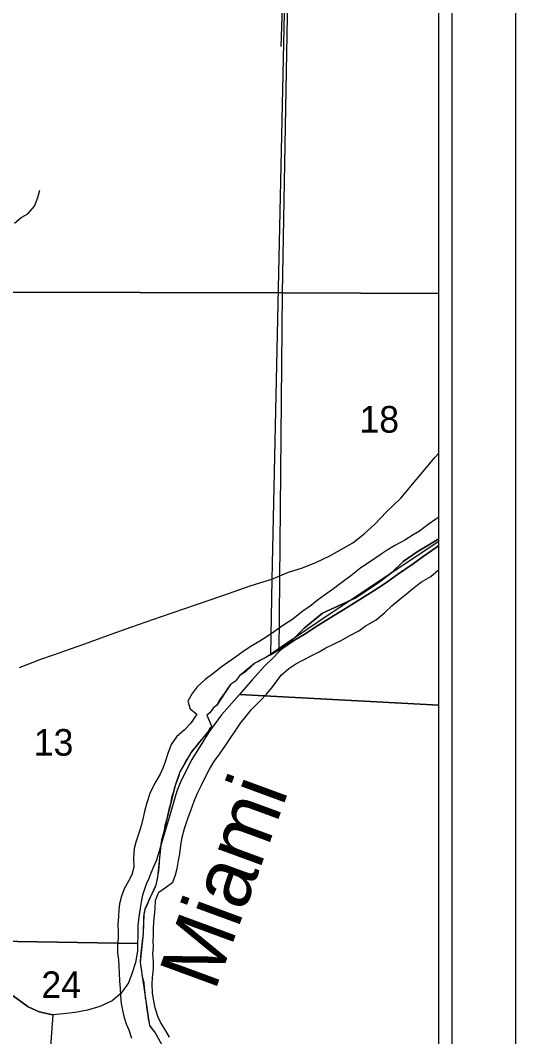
# Model space of a CAD drawing. Extents: x 0 to 34, y -2.3 to 22.
# Drawn here: x 8.222 to 9, y 17.166 to 18.764 of the extents above; entities that cross this region are included whole.
import ezdxf

# ---------------------------------------------------------------- set-up
doc = ezdxf.new("R2010")
doc.units = 0
for name, color, linetype in [('GM_X_Corporation', 7, 'Continuous'), ('GM_X_County', 7, 'Continuous'), ('GM_X_Major_River', 7, 'Continuous'), ('GM_X_Major_River_Text', 7, 'Continuous'), ('GM_X_Minor_River', 7, 'Continuous'), ('GM_X_Section', 7, 'Continuous'), ('GM_X_Section_Text', 7, 'Continuous'), ('GM_X_State_Route', 7, 'Continuous'), ('GM_X_Township', 7, 'Continuous'), ('GM_X_Township_Road', 7, 'Continuous'), ('SH_Data', 7, 'Continuous')]:
    doc.layers.add(name, color=color, linetype=linetype)

msp = doc.modelspace()

# ---------------------------------------------------------------- linework, layer by layer
at = {"layer": 'GM_X_Corporation'}
for p, q in [((8.8792, 17.9444), (8.7056, 17.8282)), ((8.8792, 14.574), (8.8792, 17.9444)), ((8.7056, 17.8282), (8.6403, 17.7846)), ((8.6403, 17.7846), (8.6086, 17.7626)), ((8.5903, 17.7529), (8.5849, 17.7484)), ((8.5951, 17.755), (8.5903, 17.7529)), ((8.6013, 17.7586), (8.5951, 17.755)), ((8.6086, 17.7626), (8.6013, 17.7586)), ((8.576, 17.74), (8.5664, 17.7333)), ((8.5849, 17.7484), (8.576, 17.74)), ((8.5598, 17.7248), (8.5522, 17.7195)), ((8.5664, 17.7333), (8.5598, 17.7248)), ((8.5424, 17.7059), (8.5381, 17.6994)), ((8.5471, 17.7132), (8.5424, 17.7059)), ((8.5522, 17.7195), (8.5471, 17.7132)), ((8.5355, 17.6958), (8.5304, 17.6867)), ((8.5381, 17.6994), (8.5355, 17.6958)), ((8.5197, 17.6747), (8.5149, 17.6714)), ((8.5248, 17.6823), (8.5197, 17.6747)), ((8.5304, 17.6867), (8.5248, 17.6823)), ((8.5149, 17.6714), (8.5225, 17.6531)), ((8.5172, 17.6456), (8.5111, 17.6378)), ((8.5193, 17.6498), (8.5172, 17.6456)), ((8.5225, 17.6531), (8.5193, 17.6498)), ((8.5004, 17.6254), (8.4954, 17.6194)), ((8.5067, 17.6329), (8.5004, 17.6254)), ((8.5111, 17.6378), (8.5067, 17.6329)), ((8.4896, 17.6122), (8.4855, 17.6049)), ((8.4921, 17.616), (8.4896, 17.6122)), ((8.4954, 17.6194), (8.4921, 17.616)), ((8.4802, 17.5959), (8.4763, 17.5882)), ((8.4826, 17.6003), (8.4802, 17.5959)), ((8.4855, 17.6049), (8.4826, 17.6003)), ((8.472, 17.5813), (8.471, 17.5758)), ((8.4722, 17.582), (8.472, 17.5813)), ((8.4763, 17.5882), (8.4722, 17.582)), ((8.4649, 17.5607), (8.4637, 17.5559)), ((8.466, 17.5635), (8.4649, 17.5607)), ((8.471, 17.5758), (8.466, 17.5635)), ((8.4618, 17.5493), (8.4596, 17.5415)), ((8.4637, 17.5559), (8.4618, 17.5493)), ((8.4576, 17.532), (8.4554, 17.5231)), ((8.4596, 17.5415), (8.4576, 17.532)), ((8.4532, 17.5137), (8.4514, 17.5059)), ((8.4554, 17.5231), (8.4532, 17.5137)), ((8.4491, 17.4975), (8.4477, 17.4892)), ((8.4514, 17.5059), (8.4491, 17.4975)), ((8.4452, 17.4806), (8.4438, 17.4752)), ((8.4477, 17.4892), (8.4452, 17.4806)), ((8.4427, 17.469), (8.4408, 17.4529)), ((8.443, 17.4718), (8.4427, 17.469)), ((8.4438, 17.4752), (8.443, 17.4718)), ((8.4408, 17.4529), (8.4403, 17.4476)), ((8.4398, 17.439), (8.439, 17.4263)), ((8.4399, 17.4434), (8.4398, 17.439)), ((8.4403, 17.4476), (8.4399, 17.4434)), ((8.439, 17.4263), (8.4371, 17.4143)), ((8.4346, 17.404), (8.4311, 17.395)), ((8.4371, 17.4143), (8.4346, 17.404)), ((8.4274, 17.3881), (8.425, 17.3829)), ((8.4311, 17.395), (8.4274, 17.3881)), ((8.4217, 17.3739), (8.4177, 17.3664)), ((8.4234, 17.3799), (8.4217, 17.3739)), ((8.425, 17.3829), (8.4234, 17.3799)), ((8.416, 17.3585), (8.4154, 17.3526)), ((8.417, 17.362), (8.416, 17.3585)), ((8.4177, 17.3664), (8.417, 17.362)), ((8.4154, 17.3526), (8.4148, 17.3282)), ((8.4148, 17.3282), (8.4135, 17.3166)), ((8.4122, 17.3066), (8.4112, 17.2972)), ((8.4126, 17.311), (8.4122, 17.3066)), ((8.4135, 17.3166), (8.4126, 17.311)), ((8.4107, 17.2919), (8.4102, 17.2831)), ((8.4112, 17.2972), (8.4107, 17.2919)), ((8.4102, 17.2831), (8.4102, 17.2821)), ((8.4102, 17.2821), (8.4119, 17.273)), ((8.4119, 17.273), (8.4122, 17.2683)), ((8.4122, 17.2683), (8.4129, 17.2639)), ((8.4129, 17.2639), (8.4134, 17.2603)), ((8.4134, 17.2603), (8.4157, 17.2507)), ((8.4157, 17.2507), (8.4164, 17.2424)), ((8.4164, 17.2424), (8.4173, 17.2346)), ((8.4173, 17.2346), (8.4181, 17.2269)), ((8.4181, 17.2269), (8.419, 17.2221)), ((8.419, 17.2221), (8.4203, 17.213)), ((8.4203, 17.213), (8.4205, 17.2082)), ((8.4205, 17.2082), (8.422, 17.1994)), ((8.422, 17.1994), (8.4225, 17.1938)), ((8.4225, 17.1938), (8.4241, 17.1871)), ((8.4241, 17.1871), (8.4249, 17.1833)), ((8.4249, 17.1833), (8.4275, 17.1795)), ((8.4275, 17.1795), (8.4335, 17.1719)), ((8.4335, 17.1719), (8.4379, 17.1644))]:
    msp.add_line(p, q, dxfattribs=at)
at = {"layer": 'GM_X_County'}
msp.add_line((8.8792, 14.574), (8.8792, 20.8994), dxfattribs=at)
at = {"layer": 'GM_X_Major_River'}
for p, q in [((8.8747, 17.9795), (8.8627, 17.9707)), ((8.8792, 17.9825), (8.8747, 17.9795)), ((8.8487, 17.9604), (8.8391, 17.9546)), ((8.8627, 17.9707), (8.8487, 17.9604)), ((8.8259, 17.9462), (8.8101, 17.9379)), ((8.8391, 17.9546), (8.8259, 17.9462)), ((8.7981, 17.9306), (8.7885, 17.9244)), ((8.8101, 17.9379), (8.7981, 17.9306)), ((8.7722, 17.913), (8.7567, 17.9028)), ((8.7885, 17.9244), (8.7722, 17.913)), ((8.7567, 17.9028), (8.7411, 17.8903)), ((8.8665, 17.8892), (8.879, 17.8999)), ((8.879, 17.8999), (8.8792, 17.9)), ((8.7411, 17.8903), (8.7272, 17.8796)), ((8.8387, 17.8701), (8.8522, 17.8808)), ((8.8522, 17.8808), (8.8665, 17.8892)), ((8.7136, 17.8697), (8.6996, 17.8598)), ((8.7272, 17.8796), (8.7136, 17.8697)), ((8.8285, 17.8617), (8.8387, 17.8701)), ((8.6884, 17.8514), (8.6767, 17.8418)), ((8.6996, 17.8598), (8.6884, 17.8514)), ((8.8056, 17.8433), (8.8181, 17.8536)), ((8.8181, 17.8536), (8.8285, 17.8617)), ((8.6663, 17.8352), (8.6499, 17.822)), ((8.6767, 17.8418), (8.6663, 17.8352)), ((8.7807, 17.8211), (8.7943, 17.8325)), ((8.7943, 17.8325), (8.8056, 17.8433)), ((8.6499, 17.822), (8.6352, 17.8125)), ((8.7637, 17.8109), (8.7807, 17.8211)), ((8.6213, 17.8029), (8.6097, 17.7949)), ((8.6352, 17.8125), (8.6213, 17.8029)), ((8.7397, 17.7967), (8.7536, 17.8036)), ((8.7536, 17.8036), (8.7637, 17.8109)), ((8.5981, 17.7876), (8.5857, 17.7803)), ((8.6097, 17.7949), (8.5981, 17.7876)), ((8.715, 17.7833), (8.7258, 17.7887)), ((8.7258, 17.7887), (8.7397, 17.7967)), ((8.5733, 17.7723), (8.5597, 17.7624)), ((8.5857, 17.7803), (8.5733, 17.7723)), ((8.6807, 17.7656), (8.6915, 17.771)), ((8.6915, 17.771), (8.7019, 17.7772)), ((8.7019, 17.7772), (8.715, 17.7833)), ((8.5477, 17.7539), (8.5376, 17.7466)), ((8.5597, 17.7624), (8.5477, 17.7539)), ((8.6545, 17.7518), (8.6668, 17.7583)), ((8.6668, 17.7583), (8.6807, 17.7656)), ((8.5264, 17.7378), (8.5124, 17.7275)), ((8.5376, 17.7466), (8.5264, 17.7378)), ((8.6319, 17.7342), (8.6436, 17.7445)), ((8.6436, 17.7445), (8.6545, 17.7518)), ((8.5124, 17.7275), (8.4999, 17.7156)), ((8.617, 17.7144), (8.6244, 17.7241)), ((8.6244, 17.7241), (8.6319, 17.7342)), ((8.4917, 17.7052), (8.4852, 17.6932)), ((8.4999, 17.7156), (8.4917, 17.7052)), ((8.5989, 17.6939), (8.6087, 17.7043)), ((8.6087, 17.7043), (8.617, 17.7144)), ((8.4852, 17.6932), (8.4887, 17.6813)), ((8.5852, 17.6799), (8.5989, 17.6939)), ((8.4887, 17.6813), (8.4991, 17.6727)), ((8.4991, 17.6727), (8.4896, 17.6585)), ((8.5769, 17.6694), (8.5852, 17.6799)), ((8.4896, 17.6585), (8.4798, 17.6481)), ((8.5592, 17.6463), (8.5679, 17.6586)), ((8.5679, 17.6586), (8.5769, 17.6694)), ((8.4798, 17.6481), (8.467, 17.6374)), ((8.5517, 17.6347), (8.5592, 17.6463)), ((8.459, 17.625), (8.4537, 17.6111)), ((8.467, 17.6374), (8.459, 17.625)), ((8.543, 17.622), (8.5517, 17.6347)), ((8.4537, 17.6111), (8.45, 17.5994)), ((8.5259, 17.5977), (8.535, 17.61)), ((8.535, 17.61), (8.543, 17.622)), ((8.45, 17.5994), (8.4463, 17.5889)), ((8.5188, 17.5854), (8.5259, 17.5977)), ((8.4418, 17.5787), (8.433, 17.5641)), ((8.4463, 17.5889), (8.4418, 17.5787)), ((8.512, 17.5734), (8.5188, 17.5854)), ((8.433, 17.5641), (8.4254, 17.5483)), ((8.5059, 17.5602), (8.512, 17.5734)), ((8.4254, 17.5483), (8.4204, 17.5332)), ((8.495, 17.5358), (8.5003, 17.5486)), ((8.5003, 17.5486), (8.5059, 17.5602)), ((8.4204, 17.5332), (8.417, 17.52)), ((8.4896, 17.5215), (8.495, 17.5358)), ((8.417, 17.52), (8.4148, 17.5102)), ((8.4855, 17.5105), (8.4896, 17.5215)), ((8.4118, 17.4973), (8.4073, 17.4841)), ((8.4148, 17.5102), (8.4118, 17.4973)), ((8.4797, 17.4932), (8.4855, 17.5105)), ((8.4073, 17.4841), (8.4035, 17.4717)), ((8.4763, 17.4796), (8.4797, 17.4932)), ((8.4035, 17.4717), (8.4006, 17.4618)), ((8.4722, 17.4534), (8.4741, 17.4663)), ((8.4741, 17.4663), (8.4763, 17.4796)), ((8.4006, 17.4618), (8.3998, 17.4466)), ((8.4704, 17.4425), (8.4722, 17.4534)), ((8.3998, 17.4466), (8.4001, 17.4322)), ((8.4681, 17.4303), (8.4704, 17.4425)), ((8.3968, 17.4201), (8.3916, 17.4103)), ((8.4001, 17.4322), (8.3968, 17.4201)), ((8.4614, 17.4084), (8.4659, 17.4201)), ((8.4659, 17.4201), (8.4681, 17.4303)), ((8.3916, 17.4103), (8.3848, 17.3983)), ((8.4397, 17.393), (8.4514, 17.4015)), ((8.4514, 17.4015), (8.4614, 17.4084)), ((8.381, 17.3866), (8.3776, 17.3746)), ((8.3848, 17.3983), (8.381, 17.3866)), ((8.4344, 17.3802), (8.4397, 17.393)), ((8.3776, 17.3746), (8.3766, 17.3651)), ((8.4337, 17.3666), (8.4344, 17.3802)), ((8.376, 17.3548), (8.3752, 17.3415)), ((8.3766, 17.3651), (8.376, 17.3548)), ((8.4316, 17.3465), (8.4326, 17.3563)), ((8.4326, 17.3563), (8.4337, 17.3666)), ((8.3752, 17.3415), (8.3757, 17.3305)), ((8.4309, 17.3354), (8.4316, 17.3465)), ((8.3754, 17.321), (8.3743, 17.3092)), ((8.3757, 17.3305), (8.3754, 17.321)), ((8.4308, 17.316), (8.431, 17.3255)), ((8.431, 17.3255), (8.4309, 17.3354)), ((8.3743, 17.3092), (8.3744, 17.2978)), ((8.4302, 17.2966), (8.4309, 17.3065)), ((8.4309, 17.3065), (8.4308, 17.316)), ((8.3744, 17.2978), (8.376, 17.2867)), ((8.431, 17.2837), (8.4302, 17.2966)), ((8.376, 17.2867), (8.3768, 17.2764)), ((8.3768, 17.2764), (8.3773, 17.2661)), ((8.4311, 17.2726), (8.431, 17.2837)), ((8.3773, 17.2661), (8.3777, 17.2532)), ((8.4289, 17.2483), (8.4296, 17.259)), ((8.4296, 17.259), (8.4311, 17.2726)), ((8.3777, 17.2532), (8.3785, 17.2413)), ((8.3785, 17.2413), (8.3794, 17.2299)), ((8.4297, 17.2346), (8.4289, 17.2483)), ((8.3794, 17.2299), (8.3805, 17.2177)), ((8.4316, 17.2216), (8.4297, 17.2346)), ((8.3805, 17.2177), (8.3822, 17.2074)), ((8.4336, 17.2109), (8.4316, 17.2216)), ((8.4381, 17.1975), (8.4336, 17.2109)), ((8.3822, 17.2074), (8.3846, 17.1974)), ((8.3846, 17.1974), (8.388, 17.1859)), ((8.4428, 17.1875), (8.4381, 17.1975)), ((8.388, 17.1859), (8.3923, 17.1763)), ((8.4504, 17.1747), (8.4428, 17.1875)), ((8.3923, 17.1763), (8.3965, 17.1636)), ((8.4563, 17.165), (8.4504, 17.1747))]:
    msp.add_line(p, q, dxfattribs=at)
at = {"layer": 'GM_X_Minor_River'}
for p, q in [((8.2494, 18.485), (8.2523, 18.4964)), ((8.2335, 18.4596), (8.2444, 18.4715)), ((8.2444, 18.4715), (8.2494, 18.485)), ((8.2234, 18.4534), (8.2335, 18.4596)), ((8.2129, 18.4445), (8.2234, 18.4534))]:
    msp.add_line(p, q, dxfattribs=at)
at = {"layer": 'GM_X_Section'}
for p, q in [((8.6506, 19.3353), (8.6333, 18.3353)), ((8.6506, 19.3353), (8.6333, 18.3353)), ((8.8792, 18.3339), (8.8792, 19.3331)), ((8.6333, 18.3353), (7.6261, 18.3379)), ((7.6261, 18.3379), (8.6333, 18.3353)), ((8.6333, 18.3353), (8.6279, 17.771)), ((8.6333, 18.3353), (8.6279, 17.771)), ((8.6333, 18.3353), (8.8792, 18.3339)), ((8.8792, 18.3339), (8.6333, 18.3353)), ((8.8792, 17.9377), (8.8792, 18.3339)), ((8.8753, 17.935), (8.8545, 17.9204)), ((8.8545, 17.9204), (8.8753, 17.935)), ((8.8792, 17.9377), (8.8753, 17.935)), ((8.8753, 17.935), (8.8792, 17.9377)), ((8.8792, 17.6869), (8.8792, 17.9377)), ((8.8545, 17.9204), (8.8391, 17.9093)), ((8.8391, 17.9093), (8.8545, 17.9204)), ((8.8391, 17.9093), (8.8144, 17.8921)), ((8.8144, 17.8921), (8.8391, 17.9093)), ((8.8144, 17.8921), (8.7955, 17.8785)), ((8.7955, 17.8785), (8.8144, 17.8921)), ((8.7763, 17.8661), (8.751, 17.8504)), ((8.751, 17.8504), (8.7763, 17.8661)), ((8.7955, 17.8785), (8.7763, 17.8661)), ((8.7763, 17.8661), (8.7955, 17.8785)), ((8.751, 17.8504), (8.7329, 17.839)), ((8.7329, 17.839), (8.751, 17.8504)), ((8.7329, 17.839), (8.7141, 17.8273)), ((8.7141, 17.8273), (8.7329, 17.839)), ((8.7141, 17.8273), (8.6891, 17.812)), ((8.6891, 17.812), (8.7141, 17.8273)), ((8.6891, 17.812), (8.6679, 17.7981)), ((8.6679, 17.7981), (8.6891, 17.812)), ((8.6526, 17.789), (8.6426, 17.7824)), ((8.6426, 17.7824), (8.6526, 17.789)), ((8.6679, 17.7981), (8.6526, 17.789)), ((8.6526, 17.789), (8.6679, 17.7981)), ((8.6279, 17.771), (8.6186, 17.761)), ((8.6279, 17.771), (8.6186, 17.761)), ((8.6345, 17.7765), (8.6279, 17.771)), ((8.6279, 17.771), (8.6345, 17.7765)), ((8.6426, 17.7824), (8.6345, 17.7765)), ((8.6345, 17.7765), (8.6426, 17.7824)), ((8.6186, 17.761), (8.6054, 17.748)), ((8.6186, 17.761), (8.6054, 17.748)), ((8.6054, 17.748), (8.586, 17.7265)), ((8.6054, 17.748), (8.586, 17.7265)), ((8.586, 17.7265), (8.5662, 17.7038)), ((8.586, 17.7265), (8.5662, 17.7038)), ((8.5662, 17.7038), (8.5381, 17.6715)), ((8.5662, 17.7038), (8.5381, 17.6715)), ((8.5662, 17.7038), (8.8792, 17.6869)), ((8.8792, 17.6869), (8.5662, 17.7038)), ((8.8792, 16.6052), (8.8792, 17.6869)), ((8.5381, 17.6715), (8.5182, 17.6443)), ((8.5381, 17.6715), (8.5182, 17.6443)), ((8.5182, 17.6443), (8.5084, 17.6294)), ((8.5182, 17.6443), (8.5084, 17.6294)), ((8.5084, 17.6294), (8.4915, 17.6017)), ((8.5084, 17.6294), (8.4915, 17.6017)), ((8.4915, 17.6017), (8.4752, 17.5695)), ((8.4915, 17.6017), (8.4752, 17.5695)), ((8.472, 17.562), (8.468, 17.5519)), ((8.472, 17.562), (8.468, 17.5519)), ((8.4752, 17.5695), (8.472, 17.562)), ((8.4752, 17.5695), (8.472, 17.562)), ((8.468, 17.5519), (8.4623, 17.5338)), ((8.468, 17.5519), (8.4623, 17.5338)), ((8.4623, 17.5338), (8.4561, 17.512)), ((8.4623, 17.5338), (8.4561, 17.512)), ((8.4561, 17.512), (8.4503, 17.4928)), ((8.4561, 17.512), (8.4503, 17.4928)), ((8.4503, 17.4928), (8.4409, 17.4608)), ((8.4503, 17.4928), (8.4409, 17.4608)), ((8.438, 17.4507), (8.4352, 17.442)), ((8.438, 17.4507), (8.4352, 17.442)), ((8.4409, 17.4608), (8.438, 17.4507)), ((8.4409, 17.4608), (8.438, 17.4507)), ((8.4312, 17.4327), (8.4271, 17.4229)), ((8.4312, 17.4327), (8.4271, 17.4229)), ((8.4352, 17.442), (8.4312, 17.4327)), ((8.4352, 17.442), (8.4312, 17.4327)), ((8.4271, 17.4229), (8.4239, 17.4143)), ((8.4271, 17.4229), (8.4239, 17.4143)), ((8.4203, 17.4064), (8.4175, 17.3993)), ((8.4203, 17.4064), (8.4175, 17.3993)), ((8.4239, 17.4143), (8.4203, 17.4064)), ((8.4239, 17.4143), (8.4203, 17.4064)), ((8.4138, 17.3883), (8.4121, 17.3801)), ((8.4138, 17.3883), (8.4121, 17.3801)), ((8.4175, 17.3993), (8.4138, 17.3883)), ((8.4175, 17.3993), (8.4138, 17.3883)), ((8.4121, 17.3801), (8.4103, 17.3676)), ((8.4121, 17.3801), (8.4103, 17.3676)), ((8.4081, 17.354), (8.4067, 17.34)), ((8.4081, 17.354), (8.4067, 17.34)), ((8.4103, 17.3676), (8.4081, 17.354)), ((8.4103, 17.3676), (8.4081, 17.354)), ((8.4067, 17.34), (8.4063, 17.3237)), ((8.4067, 17.34), (8.4063, 17.3237)), ((8.4063, 17.3237), (8.406, 17.312)), ((8.4063, 17.3237), (8.406, 17.312)), ((8.406, 17.312), (8.1504, 17.3163)), ((8.1504, 17.3163), (8.406, 17.312)), ((8.406, 17.312), (8.4062, 17.3003)), ((8.406, 17.312), (8.4062, 17.3003)), ((8.4062, 17.3003), (8.4027, 17.2822)), ((8.4062, 17.3003), (8.4027, 17.2822)), ((8.4027, 17.2822), (8.397, 17.2645)), ((8.4027, 17.2822), (8.397, 17.2645)), ((8.397, 17.2645), (8.3918, 17.2506)), ((8.397, 17.2645), (8.3918, 17.2506)), ((8.3918, 17.2506), (8.3796, 17.2334)), ((8.3918, 17.2506), (8.3796, 17.2334)), ((8.2106, 17.2297), (8.2344, 17.2129)), ((8.2344, 17.2129), (8.2106, 17.2297)), ((8.3796, 17.2334), (8.3661, 17.222)), ((8.3796, 17.2334), (8.3661, 17.222)), ((8.2344, 17.2129), (8.2517, 17.2049)), ((8.2517, 17.2049), (8.2344, 17.2129)), ((8.3466, 17.213), (8.3275, 17.2074)), ((8.3466, 17.213), (8.3275, 17.2074)), ((8.3661, 17.222), (8.3466, 17.213)), ((8.3661, 17.222), (8.3466, 17.213)), ((8.2728, 17.2003), (8.2297, 16.5747)), ((8.2728, 17.2003), (8.2297, 16.5747)), ((8.2517, 17.2049), (8.2728, 17.2003)), ((8.2728, 17.2003), (8.2517, 17.2049)), ((8.2899, 17.2018), (8.2728, 17.2003)), ((8.2899, 17.2018), (8.2728, 17.2003)), ((8.3081, 17.204), (8.2899, 17.2018)), ((8.3081, 17.204), (8.2899, 17.2018)), ((8.3275, 17.2074), (8.3081, 17.204)), ((8.3275, 17.2074), (8.3081, 17.204))]:
    msp.add_line(p, q, dxfattribs=at)
at = {"layer": 'GM_X_State_Route'}
for p, q in [((8.8438, 18.041), (8.8731, 18.0763)), ((8.8731, 18.0763), (8.8792, 18.0831)), ((8.8195, 18.0126), (8.8438, 18.041)), ((8.7973, 17.9911), (8.8195, 18.0126)), ((8.7788, 17.9717), (8.7973, 17.9911)), ((8.7622, 17.9564), (8.7788, 17.9717)), ((8.7442, 17.9419), (8.7567, 17.952)), ((8.7567, 17.952), (8.7622, 17.9564)), ((8.7073, 17.9213), (8.725, 17.9313)), ((8.725, 17.9313), (8.7442, 17.9419)), ((8.6874, 17.9116), (8.7073, 17.9213)), ((8.6434, 17.8958), (8.6653, 17.9029)), ((8.6653, 17.9029), (8.6874, 17.9116)), ((8.5844, 17.8748), (8.6171, 17.8851)), ((8.6171, 17.8851), (8.6434, 17.8958)), ((8.5386, 17.8589), (8.5844, 17.8748)), ((8.4987, 17.8451), (8.5386, 17.8589)), ((8.4437, 17.8263), (8.4987, 17.8451)), ((8.3955, 17.8096), (8.4437, 17.8263)), ((8.3588, 17.7964), (8.3955, 17.8096)), ((8.3231, 17.7834), (8.3588, 17.7964)), ((8.2739, 17.766), (8.3007, 17.7754)), ((8.3007, 17.7754), (8.3231, 17.7834)), ((8.2204, 17.7459), (8.2543, 17.7593)), ((8.2543, 17.7593), (8.2739, 17.766))]:
    msp.add_line(p, q, dxfattribs=at)
at = {"layer": 'GM_X_Township'}
for p, q in [((8.8792, 17.9482), (8.8792, 20.8994)), ((8.6474, 19.2909), (8.6171, 17.8851)), ((8.6474, 19.2909), (8.6171, 17.8851)), ((8.8454, 17.9281), (8.8792, 17.9482)), ((8.8792, 17.9482), (8.8454, 17.9281)), ((8.8792, 14.574), (8.8792, 17.9482)), ((8.8234, 17.9128), (8.8454, 17.9281)), ((8.8454, 17.9281), (8.8234, 17.9128)), ((8.8055, 17.8956), (8.8234, 17.9128)), ((8.8234, 17.9128), (8.8055, 17.8956)), ((8.6171, 17.8851), (8.6148, 17.7662)), ((8.6171, 17.8851), (8.6148, 17.7662)), ((8.7842, 17.879), (8.8055, 17.8956)), ((8.8055, 17.8956), (8.7842, 17.879)), ((8.748, 17.8553), (8.7842, 17.879)), ((8.7842, 17.879), (8.748, 17.8553)), ((8.6965, 17.8314), (8.748, 17.8553)), ((8.748, 17.8553), (8.6965, 17.8314)), ((8.6678, 17.8082), (8.6965, 17.8314)), ((8.6965, 17.8314), (8.6678, 17.8082)), ((8.6488, 17.7889), (8.6678, 17.8082)), ((8.6678, 17.8082), (8.6488, 17.7889)), ((8.635, 17.778), (8.6488, 17.7889)), ((8.6488, 17.7889), (8.635, 17.778)), ((8.6148, 17.7662), (8.635, 17.778)), ((8.635, 17.778), (8.6148, 17.7662)), ((8.5903, 17.7529), (8.5664, 17.7333)), ((8.5903, 17.7529), (8.5664, 17.7333)), ((8.6148, 17.7662), (8.5903, 17.7529)), ((8.6148, 17.7662), (8.5903, 17.7529)), ((8.5598, 17.7248), (8.5522, 17.7195)), ((8.5598, 17.7248), (8.5522, 17.7195)), ((8.5664, 17.7333), (8.5598, 17.7248)), ((8.5664, 17.7333), (8.5598, 17.7248)), ((8.5522, 17.7195), (8.5304, 17.6867)), ((8.5522, 17.7195), (8.5304, 17.6867)), ((8.5197, 17.6747), (8.5149, 17.6714)), ((8.5197, 17.6747), (8.5149, 17.6714)), ((8.5248, 17.6823), (8.5197, 17.6747)), ((8.5248, 17.6823), (8.5197, 17.6747)), ((8.5304, 17.6867), (8.5248, 17.6823)), ((8.5304, 17.6867), (8.5248, 17.6823)), ((8.5149, 17.6714), (8.5225, 17.6531)), ((8.5149, 17.6714), (8.5225, 17.6531)), ((8.5225, 17.6531), (8.4896, 17.6122)), ((8.5225, 17.6531), (8.4896, 17.6122)), ((8.4896, 17.6122), (8.4722, 17.582)), ((8.4896, 17.6122), (8.4722, 17.582)), ((8.4722, 17.582), (8.4649, 17.5607)), ((8.4722, 17.582), (8.4649, 17.5607)), ((8.4649, 17.5607), (8.443, 17.4718)), ((8.4649, 17.5607), (8.443, 17.4718)), ((8.443, 17.4718), (8.4375, 17.4164)), ((8.443, 17.4718), (8.4375, 17.4164)), ((8.4346, 17.404), (8.4177, 17.3664)), ((8.4346, 17.404), (8.4177, 17.3664)), ((8.4375, 17.4164), (8.4346, 17.404)), ((8.4375, 17.4164), (8.4346, 17.404)), ((8.416, 17.3585), (8.4148, 17.3282)), ((8.416, 17.3585), (8.4148, 17.3282)), ((8.4177, 17.3664), (8.416, 17.3585)), ((8.4177, 17.3664), (8.416, 17.3585)), ((8.4148, 17.3282), (8.4102, 17.2821)), ((8.4148, 17.3282), (8.4102, 17.2821)), ((8.4102, 17.2821), (8.4249, 17.1833)), ((8.4102, 17.2821), (8.4249, 17.1833)), ((8.4249, 17.1833), (8.4335, 17.1719)), ((8.4249, 17.1833), (8.4335, 17.1719)), ((8.4335, 17.1719), (8.4549, 17.1338)), ((8.4335, 17.1719), (8.4549, 17.1338))]:
    msp.add_line(p, q, dxfattribs=at)
at = {"layer": 'GM_X_Township_Road'}
msp.add_line((8.637, 18.9012), (8.631, 18.7227), dxfattribs=at)
at = {"layer": 'SH_Data'}
for p, q in [((9, 21), (9, 14)), ((8.9, 20.9), (8.9, 14.1))]:
    msp.add_line(p, q, dxfattribs=at)

# ---------------------------------------------------------------- texts
at = {"layer": 'GM_X_Major_River_Text'}
msp.add_text('Miami', height=0.09469, rotation=69.8181, dxfattribs=at).set_placement((8.5273, 17.2357))
at = {"layer": 'GM_X_Section_Text'}
for s, p in [('18', (8.7546, 18.1154)), ('13', (8.243, 17.6075)), ('24', (8.255, 17.2265))]:
    msp.add_text(s, height=0.04186, rotation=0, dxfattribs=at).set_placement(p)

doc.saveas('drawing.dxf')
